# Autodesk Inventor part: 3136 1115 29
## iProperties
Shininess: 20.0
Length Units: 11269
Angle Units: 11279
Time Units: 11290
Mass Units: 11283
Length Display Precision: 3
Angle Display Precision: 2
Compacted: True
Created: 2000-11
Part Number: 3136 1115 29
Material: Steel, Mild
Document SubType Name: Modeling
Designer: Joe M
Engineer: Joe M
Density: 0.0
Volumn: 0.0
Area: 0.0
PropertySet Name: Model Information
Control State: 0
Master: False
Checked Out: False
Last Check In By: brpog
Last Check In Date: 2001-02-28
Author: Joe M
